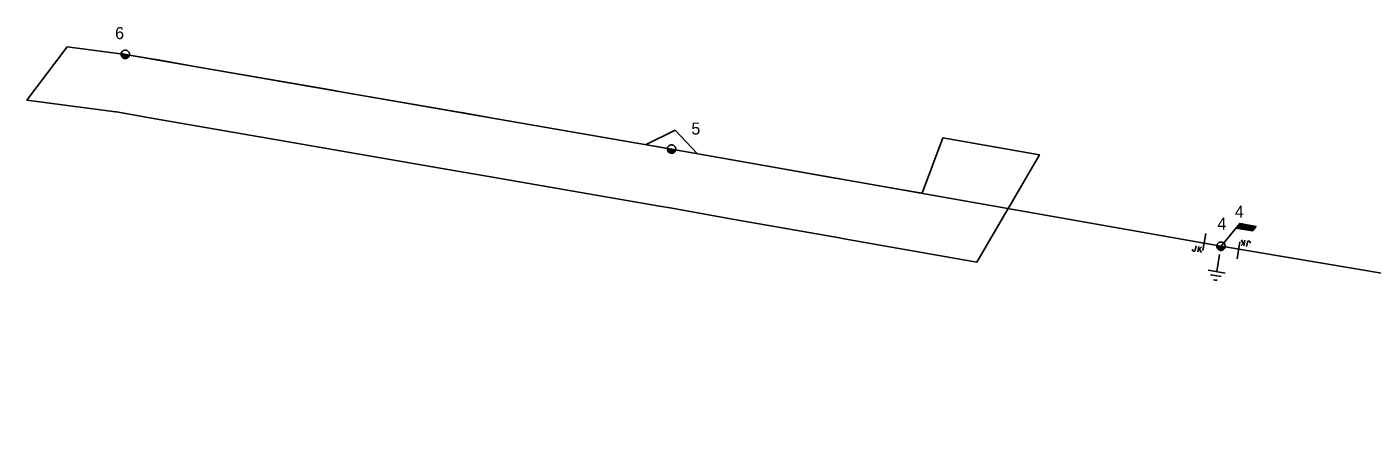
# Model space of a CAD drawing. Extents: x -540879 to -537255, y -1184046 to -1180016.
# Drawn here: x -539430.9 to -539234.9, y -1180586.7 to -1180525.1 of the extents above; entities that cross this region are included whole.
import ezdxf

# ---------------------------------------------------------------- set-up
doc = ezdxf.new("R2010")
doc.units = 0
for name, color, linetype in [('Default', 7, 'Continuous'), ('Vrstva 11', 7, 'Continuous'), ('Vrstva 12', 7, 'Continuous'), ('Vrstva 13', 7, 'Continuous'), ('Vrstva 14', 7, 'Continuous'), ('Vrstva 15', 7, 'Continuous'), ('Vrstva 18', 7, 'Continuous'), ('Vrstva 2', 7, 'Continuous'), ('Vrstva 35', 7, 'Continuous'), ('Vrstva 4', 7, 'Continuous')]:
    doc.layers.add(name, color=color, linetype=linetype)

# ---------------------------------------------------------------- blocks, each defined once
blk = doc.blocks.new('VN840')
at = {"layer": 'Vrstva 15'}
for points in [[(-0.01, 1.41), (-0.01, -1.09)], [(-1.51, -1.24), (-1.51, -1.15)], [(-1.48, -1.35), (-1.51, -1.24)], [(-1.33, -1.42), (-1.48, -1.35)], [(-1.27, -1.42), (-1.33, -1.42)], [(-1.13, -1.35), (-1.27, -1.42)], [(-1.09, -1.24), (-1.13, -1.35)], [(-1.09, -0.59), (-1.09, -1.24)], [(-0.68, -0.59), (-0.68, -1.42)], [(-0.68, -1.11), (-0.27, -0.59)], [(-0.54, -0.94), (-0.2, -1.42)]]:
    blk.add_lwpolyline(points, dxfattribs=at)
blk = doc.blocks.new('VN860')
at = {"layer": 'Vrstva 15'}
for points in [[(-3.74, 0), (0.01, 2.82)], [(0.01, 2.82), (3.76, 0)]]:
    blk.add_lwpolyline(points, dxfattribs=at)
blk = doc.blocks.new('VN440')
at = {"layer": 'Vrstva 2'}
for points in [[(1.22, 0), (1.21, 0.13), (1.19, 0.25), (1.16, 0.38), (1.11, 0.5), (1.05, 0.61), (0.98, 0.72), (0.9, 0.82), (0.81, 0.91), (0.71, 0.99), (0.6, 1.06), (0.49, 1.12), (0.37, 1.16), (0.25, 1.2), (0.12, 1.22), (-0.01, 1.22), (-0.14, 1.22), (-0.26, 1.2), (-0.39, 1.16), (-0.51, 1.12), (-0.62, 1.06), (-0.73, 0.99), (-0.83, 0.91), (-0.92, 0.82), (-1, 0.72), (-1.07, 0.61), (-1.13, 0.5), (-1.18, 0.38), (-1.21, 0.25), (-1.23, 0.13), (-1.24, 0), (-1.23, -0.13), (-1.21, -0.26), (-1.18, -0.38), (-1.13, -0.5), (-1.07, -0.62), (-1, -0.73), (-0.92, -0.83), (-0.83, -0.92), (-0.73, -1), (-0.62, -1.07), (-0.51, -1.13), (-0.39, -1.17), (-0.26, -1.2), (-0.14, -1.23), (-0.01, -1.23), (0.12, -1.23), (0.25, -1.2), (0.37, -1.17), (0.49, -1.13), (0.6, -1.07), (0.71, -1), (0.81, -0.92), (0.9, -0.83), (0.98, -0.73), (1.05, -0.62), (1.11, -0.5), (1.16, -0.38), (1.19, -0.26), (1.21, -0.13), (1.22, 0)], [(-1.24, 0), (1.22, 0)], [(-1.18, -0.34), (1.1, -0.34)], [(-1.01, -0.63), (0.97, -0.63)], [(-0.74, -0.92), (0.68, -0.92)]]:
    blk.add_lwpolyline(points, dxfattribs=at)
blk = doc.blocks.new('VN810')
at = {"layer": 'Vrstva 14'}
for points in [[(0, -1.25), (0, -3.75)], [(1.25, -3.75), (-1.25, -3.75)], [(0.77, -4.37), (-0.8, -4.37)], [(0, -5), (-0.25, -5)], [(0.27, -5), (0, -5)]]:
    blk.add_lwpolyline(points, dxfattribs=at)
blk = doc.blocks.new('VN001')
at = {"layer": 'Default'}
for p, q in [((1.73, 3.03), (4.14, 3.03)), ((1.76, 3.08), (4.17, 3.08)), ((1.79, 3.13), (4.2, 3.13)), ((1.82, 3.18), (4.23, 3.18)), ((1.85, 3.23), (4.26, 3.23)), ((1.87, 3.28), (4.29, 3.28)), ((1.9, 3.33), (4.32, 3.33)), ((1.93, 3.38), (4.35, 3.38)), ((1.96, 3.43), (4.37, 3.43)), ((1.99, 3.48), (4.4, 3.48)), ((2.02, 3.53), (4.43, 3.53)), ((2.05, 3.58), (4.46, 3.58)), ((2.07, 3.63), (4.49, 3.63)), ((2.1, 3.68), (4.52, 3.68)), ((2.13, 3.73), (2.54, 3.73))]:
    blk.add_line(p, q, dxfattribs=at)
blk.add_lwpolyline([(2.13, 3.73), (0, 0)], dxfattribs=at)
blk.add_lwpolyline([(4.55, 3.73), (2.13, 3.73), (1.7, 2.98), (4.12, 2.99)], close=True, dxfattribs=at)

msp = doc.modelspace()

# ---------------------------------------------------------------- linework, layer by layer
at = {"layer": 'Vrstva 35'}
msp.add_lwpolyline([(-539425.09, -1180528), (-539416.6, -1180529.11), (-539412.5, -1180529.82), (-539412.13, -1180529.88), (-539405.96, -1180530.96), (-539387.5, -1180534.16), (-539385.91, -1180534.43), (-539384.65, -1180534.65), (-539368.23, -1180537.5), (-539367.29, -1180537.66), (-539363.35, -1180538.35), (-539363.04, -1180538.4), (-539362.5, -1180538.5), (-539342.04, -1180542.04), (-539337.5, -1180542.83), (-539336.98, -1180542.92), (-539320.78, -1180545.79), (-539313.41, -1180547.09), (-539312.5, -1180547.25), (-539304.18, -1180548.72), (-539300.48, -1180549.37), (-539297.46, -1180541.28), (-539292.21, -1180542.21), (-539287.5, -1180543.04), (-539283.37, -1180543.77), (-539287.5, -1180550.85), (-539287.93, -1180551.59), (-539292.48, -1180559.42), (-539306.88, -1180556.87), (-539311.82, -1180556), (-539312.5, -1180555.88), (-539326.45, -1180553.42), (-539328.12, -1180553.12), (-539337.5, -1180551.46), (-539338.44, -1180551.29), (-539349.4, -1180549.4), (-539362.5, -1180547.12), (-539370.7, -1180545.7), (-539387.5, -1180542.78), (-539392.01, -1180542), (-539412.5, -1180538.45), (-539413.31, -1180538.31), (-539417.88, -1180537.51), (-539418.03, -1180537.5), (-539430.95, -1180535.81)], close=True, dxfattribs=at)
at = {"layer": 'Vrstva 4'}
for points in [[(-539000.66, -1180526.37), (-538996.91, -1180550.03), (-539018.78, -1180586.66), (-539193.69, -1180567.72), (-539256.89, -1180557.08)], [(-539256.89, -1180557.08), (-539336.98, -1180542.92), (-539416.6, -1180529.11), (-539425.09, -1180528)]]:
    msp.add_lwpolyline(points, dxfattribs=at)

# ---------------------------------------------------------------- block references
at = {"layer": 'Vrstva 11', "rotation": -9.842086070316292}
msp.add_blockref('VN001', (-539256.89, -1180557.08), dxfattribs=at)
at = {"layer": 'Vrstva 13', "xscale": 0.5}
for p, yscale, rotation in [((-539416.6, -1180529.11), 0.49999999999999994, -9.839412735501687), ((-539336.98, -1180542.92), 0.5, -10.023488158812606), ((-539256.89, -1180557.08), 0.5, -9.553857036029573)]:
    msp.add_blockref('VN440', p, dxfattribs=dict(at, yscale=yscale, rotation=rotation))
at = {"layer": 'Vrstva 15', "rotation": -9.842086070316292}
msp.add_blockref('VN810', (-539256.89, -1180557.08), dxfattribs=at)
at = {"layer": 'Vrstva 18'}
for name, p, rotation in [('VN860', (-539336.98, -1180542.92), -10.02359483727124), ('VN840', (-539259.36, -1180556.64), -10.02359483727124), ('VN840', (-539254.34, -1180557.51), 170.4427149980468)]:
    msp.add_blockref(name, p, dxfattribs=dict(at, rotation=rotation))

# ---------------------------------------------------------------- texts
at = {"layer": 'Vrstva 12'}
msp.add_text('4', height=1.75, dxfattribs=at).set_placement((-539254.88, -1180552.9))
at = {"layer": 'Vrstva 14'}
for s, p in [('6', (-539418.09, -1180526.89)), ('5', (-539334.1, -1180540.8)), ('4', (-539257.43, -1180554.67))]:
    msp.add_text(s, height=1.75, dxfattribs=at).set_placement(p)

doc.saveas('drawing.dxf')
